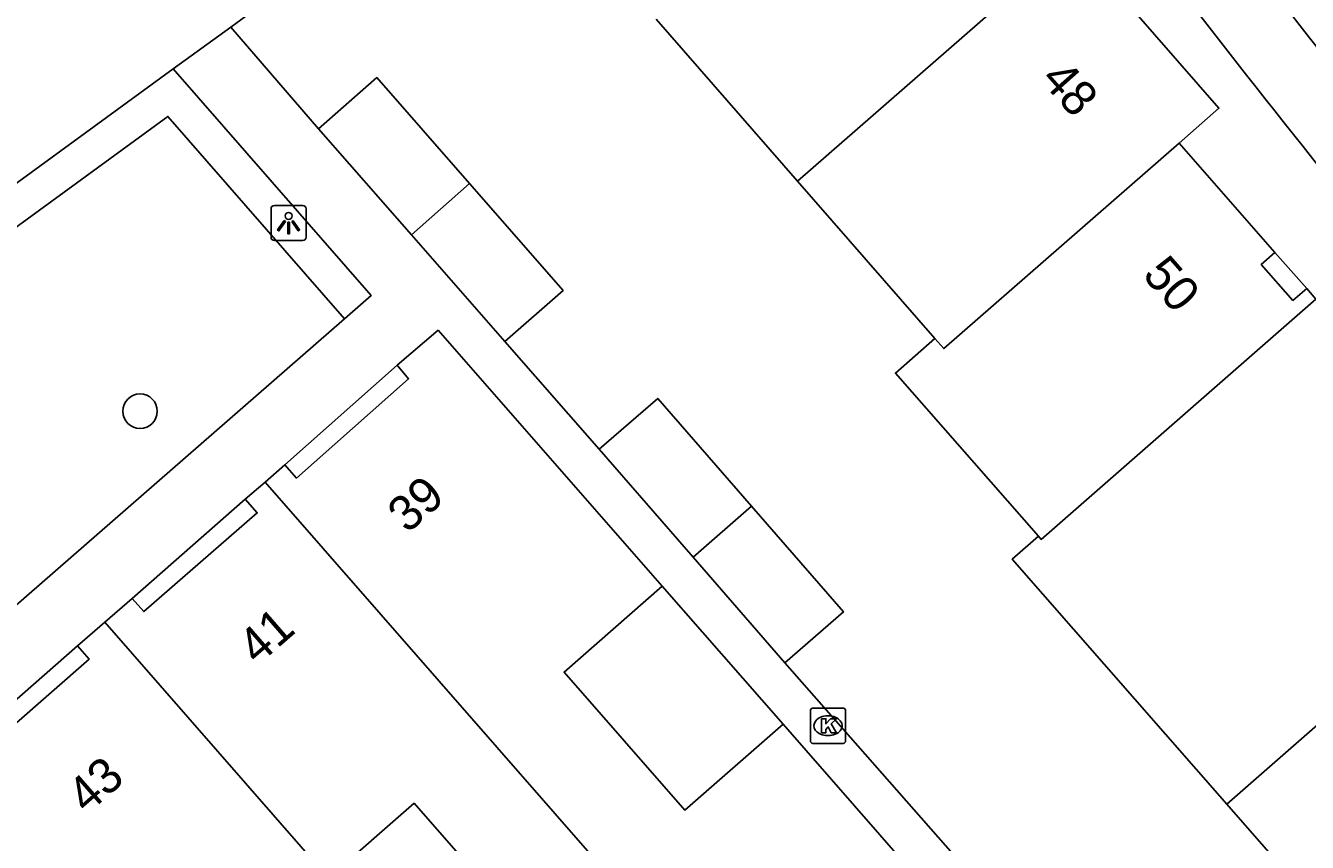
# Model space of a CAD drawing. Extents: x 161772 to 163123, y 383092 to 383917.
# Drawn here: x 162216.99 to 162253.34, y 383293.68 to 383316.84 of the extents above; entities that cross this region are included whole.
import ezdxf

# ---------------------------------------------------------------- set-up
doc = ezdxf.new("R2010")
doc.units = 0
for name, color, linetype in [('IMGEO_Boom', 7, 'Continuous'), ('IMGEO_Groenvoorziening', 7, 'Continuous'), ('IMGEO_Kolk', 7, 'Continuous'), ('IMGEO_Lichtpunt', 7, 'Continuous'), ('IMGEO_Muur', 7, 'Continuous'), ('IMGEO_Pand', 7, 'Continuous'), ('IMGEO_Pand_nummerreeks', 7, 'Continuous'), ('IMGEO_Pand_overbouw', 7, 'Continuous'), ('IMGEO_Voetpad_open', 7, 'Continuous')]:
    doc.layers.add(name, color=color, linetype=linetype)

msp = doc.modelspace()

# ---------------------------------------------------------------- linework, layer by layer
at = {"layer": 'IMGEO_Boom'}
msp.add_circle((162220.236, 383305.903), 0.489, dxfattribs=at)
at = {"layer": 'IMGEO_Groenvoorziening'}
msp.add_lwpolyline([(162214.121, 383298.146), (162208.21, 383304.915), (162221.026, 383314.264), (162226.033, 383308.526)], dxfattribs=at)
at = {"layer": 'IMGEO_Kolk'}
for p, q in [((162239.242, 383296.558), (162239.242, 383297.41)), ((162239.317, 383297.484), (162240.169, 383297.484)), ((162240.243, 383297.41), (162240.243, 383296.558)), ((162239.73, 383297.264), (162239.755, 383297.264)), ((162239.753, 383296.704), (162239.728, 383296.704)), ((162240.169, 383296.484), (162239.317, 383296.484))]:
    msp.add_line(p, q, dxfattribs=at)
for points in [[(162239.242, 383296.558), (162239.242, 383297.41)], [(162239.317, 383297.484), (162240.169, 383297.484)], [(162240.243, 383297.41), (162240.243, 383296.558)], [(162239.563, 383297.184), (162239.686, 383297.184), (162239.686, 383297.033), (162239.816, 383297.184), (162239.98, 383297.184), (162239.834, 383297.033), (162239.987, 383296.784), (162239.835, 383296.784), (162239.75, 383296.948), (162239.686, 383296.881), (162239.686, 383296.784), (162239.563, 383296.784), (162239.563, 383297.184)], [(162240.169, 383296.484), (162239.317, 383296.484)]]:
    msp.add_lwpolyline(points, dxfattribs=at)
for centre, start, end in [((162239.319, 383297.408), 91.552, 178.448), ((162239.319, 383297.408), 91.552, 178.448), ((162240.167, 383297.408), 1.552, 88.448), ((162240.167, 383297.408), 1.552, 88.448), ((162239.319, 383296.56), 181.552, 268.448), ((162239.319, 383296.56), 181.552, 268.448), ((162240.167, 383296.56), 271.552, 358.448), ((162240.167, 383296.56), 271.552, 358.448)]:
    msp.add_arc(centre, 0.0765, start, end, dxfattribs=at)
for centre, major_axis, ratio, start_param, end_param in [((162239.729, 383296.984), (-0.387, 0.002), 0.722429, 4.712389, 7.853982), ((162239.754, 383296.984), (-0.39, 0.002), 0.717154, 1.570796, 4.712389)]:
    msp.add_ellipse(centre, major_axis=major_axis, ratio=ratio, start_param=start_param, end_param=end_param, dxfattribs=at)
at = {"layer": 'IMGEO_Lichtpunt'}
for p, q in [((162223.949, 383311.643), (162223.949, 383310.836)), ((162223.949, 383311.643), (162223.949, 383310.836)), ((162224.851, 383311.738), (162224.043, 383311.738)), ((162224.851, 383311.738), (162224.043, 383311.738)), ((162224.945, 383310.836), (162224.945, 383311.643)), ((162224.945, 383310.836), (162224.945, 383311.643)), ((162224.043, 383310.742), (162224.851, 383310.742)), ((162224.043, 383310.742), (162224.851, 383310.742))]:
    msp.add_line(p, q, dxfattribs=at)
for points in [[(162224.323, 383311.307), (162224.362, 383311.279), (162224.174, 383311.017), (162224.136, 383311.044), (162224.323, 383311.307)], [(162224.425, 383311.259), (162224.472, 383311.259), (162224.472, 383310.937), (162224.425, 383310.937), (162224.425, 383311.259)], [(162224.535, 383311.279), (162224.573, 383311.306), (162224.76, 383311.044), (162224.721, 383311.016), (162224.535, 383311.279)]]:
    msp.add_lwpolyline(points, dxfattribs=at)
msp.add_circle((162224.448, 383311.441), 0.0994, dxfattribs=at)
for centre, start, end in [((162224.043, 383311.643), 90, 180), ((162224.043, 383311.643), 90, 180), ((162224.851, 383311.643), 0, 90), ((162224.851, 383311.643), 0, 90), ((162224.043, 383310.836), 180, 270), ((162224.043, 383310.836), 180, 270), ((162224.851, 383310.836), 270, 0), ((162224.851, 383310.836), 270, 360)]:
    msp.add_arc(centre, 0.0946, start, end, dxfattribs=at)
at = {"layer": 'IMGEO_Muur'}
for points in [[(162222.811, 383316.795), (162230.269, 383322.276)], [(162225.293, 383313.914), (162222.811, 383316.795)], [(162233.257, 383304.822), (162230.577, 383307.879)], [(162243.557, 383293.038), (162238.521, 383298.769)]]:
    msp.add_lwpolyline(points, dxfattribs=at)
at = {"layer": 'IMGEO_Pand'}
for points in [[(162246.65, 383319.213), (162238.88, 383312.423)], [(162249.698, 383313.507), (162250.829, 383314.493), (162247.83, 383317.934), (162247.446, 383317.58), (162246.543, 383318.623), (162246.928, 383318.957), (162246.65, 383319.213)], [(162234.866, 383317.016), (162238.88, 383312.423)], [(162229.58, 383312.357), (162226.948, 383315.363), (162225.293, 383313.914)], [(162227.932, 383310.9), (162225.293, 383313.914)], [(162249.698, 383313.507), (162243.026, 383307.677), (162242.773, 383307.967)], [(162253.578, 383309.078), (162253.321, 383309.381), (162252.924, 383309.045), (162252.026, 383310.062), (162252.417, 383310.405), (162249.698, 383313.507)], [(162227.932, 383310.9), (162229.58, 383312.357)], [(162230.577, 383307.879), (162232.232, 383309.328), (162229.58, 383312.357)], [(162238.88, 383312.423), (162242.773, 383307.967)], [(162230.577, 383307.879), (162227.932, 383310.9)], [(162245.711, 383302.357), (162245.792, 383302.265), (162253.578, 383309.078)], [(162227.524, 383307.206), (162228.686, 383308.197), (162235.04, 383300.94)], [(162242.773, 383307.967), (162241.653, 383306.985), (162245.711, 383302.357)], [(162227.524, 383307.206), (162227.848, 383306.825), (162224.671, 383304.006), (162224.343, 383304.383)], [(162237.575, 383303.209), (162234.917, 383306.266), (162233.257, 383304.822)], [(162235.915, 383301.766), (162233.257, 383304.822)], [(162223.78, 383303.895), (162224.343, 383304.383)], [(162223.217, 383303.406), (162223.78, 383303.895)], [(162236.94, 383288.841), (162223.78, 383303.895)], [(162223.217, 383303.406), (162223.56, 383303.017), (162220.342, 383300.219), (162220.014, 383300.596)], [(162235.915, 383301.766), (162237.575, 383303.209)], [(162238.521, 383298.769), (162240.181, 383300.213), (162237.575, 383303.209)], [(162245.711, 383302.357), (162244.966, 383301.706), (162251.05, 383294.755)], [(162238.521, 383298.769), (162235.915, 383301.766)], [(162251.05, 383294.755), (162258.768, 383301.51)], [(162235.04, 383300.94), (162232.257, 383298.505), (162235.685, 383294.588), (162238.469, 383297.024)], [(162219.239, 383299.921), (162220.014, 383300.596)], [(162218.463, 383299.245), (162219.239, 383299.921)], [(162225.583, 383292.664), (162219.239, 383299.921)], [(162218.463, 383299.245), (162218.792, 383298.868), (162215.582, 383296.062), (162215.253, 383296.438)], [(162238.469, 383297.024), (162241.864, 383293.146), (162236.94, 383288.841)], [(162228.881, 383288.891), (162231.308, 383291.016), (162228.008, 383294.787), (162225.583, 383292.664)], [(162251.05, 383294.755), (162257.156, 383287.777), (162257.898, 383288.439), (162258.1, 383288.208)]]:
    msp.add_lwpolyline(points, dxfattribs=at)
at = {"layer": 'IMGEO_Pand_overbouw'}
msp.add_lwpolyline([(162253.321, 383309.381), (162252.417, 383310.405), (162252.026, 383310.062), (162252.924, 383309.045)], close=True, dxfattribs=at)
at = {"layer": 'IMGEO_Voetpad_open'}
for points in [[(162222.811, 383316.795), (162230.269, 383322.276)], [(162222.811, 383316.795), (162221.177, 383315.612)], [(162225.293, 383313.914), (162222.811, 383316.795)], [(162221.177, 383315.612), (162206.739, 383305.08)], [(162226.033, 383308.526), (162226.787, 383309.183), (162221.177, 383315.612)], [(162214.121, 383298.146), (162226.033, 383308.526)], [(162233.257, 383304.822), (162230.577, 383307.879)], [(162224.343, 383304.383), (162227.524, 383307.206)], [(162220.014, 383300.596), (162223.217, 383303.406)], [(162235.04, 383300.94), (162238.469, 383297.024)], [(162215.253, 383296.438), (162218.463, 383299.245)], [(162243.557, 383293.038), (162238.521, 383298.769)]]:
    msp.add_lwpolyline(points, dxfattribs=at)
for centre, radius, start, end in [((162521.109, 383526.552), 342.343, 215.04537, 219.66046), ((162457.082, 383476.267), 258.872, 215.39009, 219.17644)]:
    msp.add_arc(centre, radius, start, end, dxfattribs=at)

# ---------------------------------------------------------------- texts
at = {"layer": 'IMGEO_Pand_nummerreeks'}
for s, rotation, p in [('48', 311.5117, (162245.74, 383315.293)), ('50', 311.2206, (162248.63, 383309.749)), ('39', 41.5853, (162227.819, 383302.413)), ('41', 41.0066, (162223.565, 383298.675)), ('43', 41.167, (162218.726, 383294.453))]:
    msp.add_text(s, height=1, rotation=rotation, dxfattribs=at).set_placement(p)

doc.saveas('drawing.dxf')
